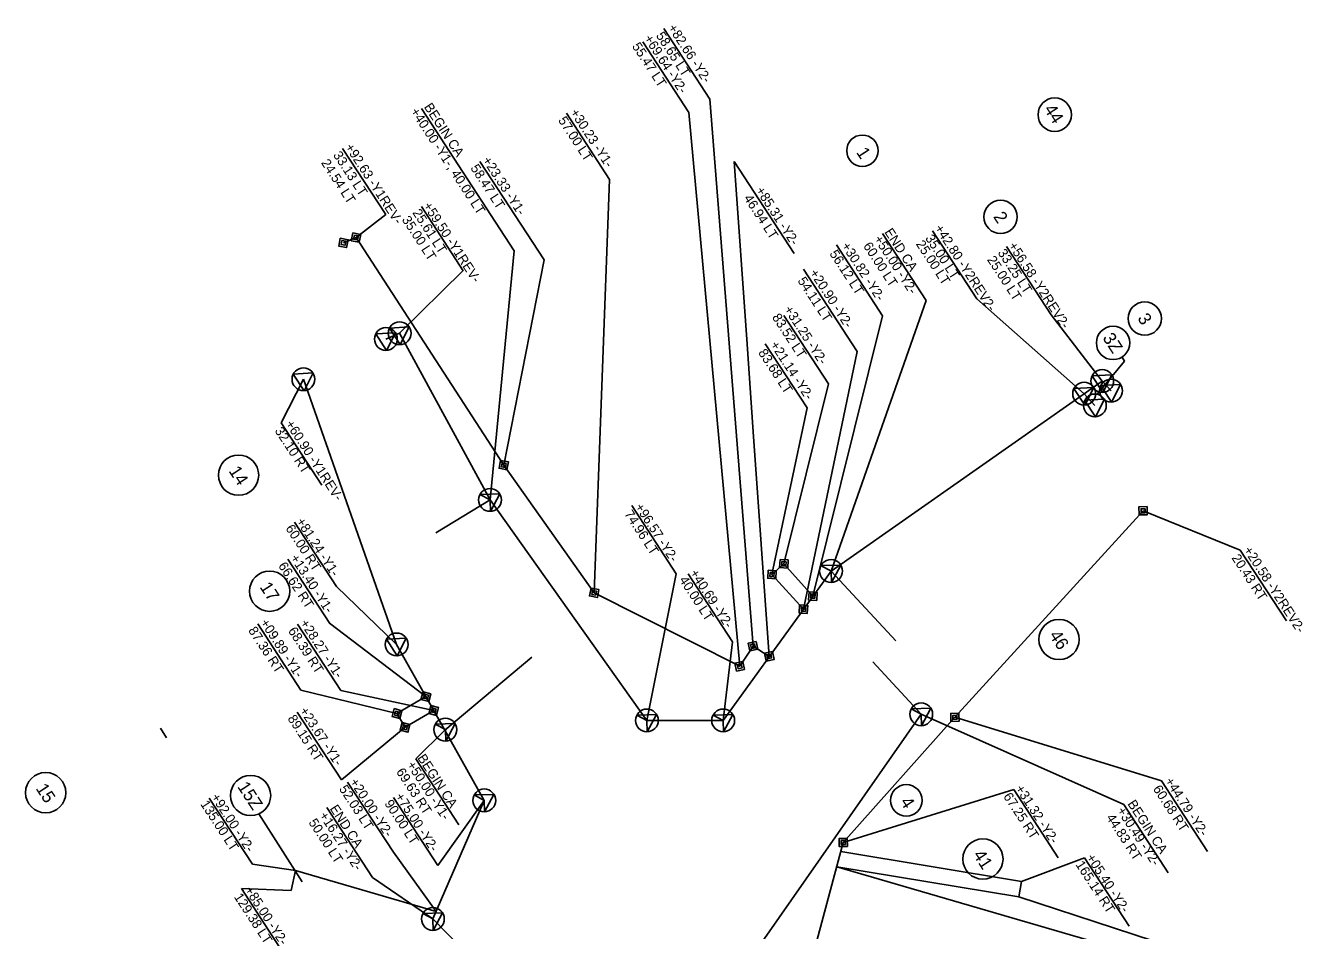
# Model space of a CAD drawing. Extents: x 1638966 to 1642158, y 841755 to 844938.
# Drawn here: x 1640014 to 1640818, y 843723 to 844293 of the extents above; entities that cross this region are included whole.
import ezdxf

# ---------------------------------------------------------------- set-up
doc = ezdxf.new("R2010")
doc.units = 0
for name, color, linetype in [('Exist Building', 7, 'Continuous'), ('Exist Guardrail Text', 7, 'Continuous'), ('Exist Other Culture Fence Line Text', 7, 'Continuous'), ('Exist Structure Major Deck Tunnel Box Culvert Text', 7, 'Continuous'), ('Exist Structure Minor Pipes CMP 18 Inch', 7, 'Continuous'), ('Exist Structure Minor Pipes CMP 18 Inch Text', 7, 'Continuous'), ('Exist Structure Minor Pipes CMP 24 Inch', 7, 'Continuous'), ('Exist Structure Minor Pipes RCP 24 Inch', 7, 'Continuous'), ('P_RDY_ROW_RW_CA_Lines', 7, 'Continuous'), ('Prop ROW Marker CELL', 7, 'Continuous')]:
    doc.layers.add(name, color=color, linetype=linetype)

msp = doc.modelspace()

# ---------------------------------------------------------------- linework, layer by layer
at = {"layer": 'Exist Building'}
for p, q in [((1640098.49, 843850.51), (1640102.45, 843844.41)), ((1640160.46, 843796.51), (1640187.9, 843753.69))]:
    msp.add_line(p, q, dxfattribs=at)
for centre, radius in [((1640662.07, 844237.1), 10.51), ((1640540.9, 844214.37), 9.91), ((1640627.96, 844172.72), 10.51), ((1640718.81, 844108.67), 10.51), ((1640698.83, 844093.26), 10.51), ((1640147.77, 844009.98), 12.69), ((1640167.33, 843936.85), 12.69), ((1640664.81, 843906.43), 12.69), ((1640026.21, 843809.9), 12.69), ((1640155.35, 843808.12), 12.69), ((1640568.57, 843805.06), 9.91), ((1640616.83, 843768.09), 12.69)]:
    msp.add_circle(centre, radius, dxfattribs=at)
at = {"layer": 'Exist Guardrail Text'}
for p, q in [((1640321.54, 844151.32), (1640263.07, 844240.92)), ((1640289.4, 844138.68), (1640262.98, 844179.16)), ((1640613.02, 844121.03), (1640585.03, 844163.91)), ((1640581.08, 844120.02), (1640553.55, 844162.22)), ((1640321.54, 844151.32), (1640306.22, 843994.38)), ((1640659.82, 844110.96), (1640631.72, 844154.04)), ((1640581.08, 844120.02), (1640521.15, 843949.58)), ((1640613.02, 844121.03), (1640680.64, 844061.31)), ((1640704.78, 844083.88), (1640706.1, 844081.85)), ((1640706.1, 844081.85), (1640689.1, 844061.24)), ((1640174.6, 844042.97), (1640188.67, 844070.41)), ((1640200.23, 844003.69), (1640174.6, 844042.97)), ((1640423.5, 843947.86), (1640395.51, 843990.75)), ((1640209.4, 843939.8), (1640182.99, 843980.29)), ((1640423.5, 843947.86), (1640405.08, 843855.41)), ((1640459.04, 843904.88), (1640431.05, 843947.77)), ((1640459.04, 843904.88), (1640453.14, 843855.41)), ((1640705.63, 843802.37), (1640577.95, 843859.33)), ((1640286.59, 843789.59), (1640259.38, 843831.27)), ((1640273.3, 843764.04), (1640245.31, 843806.93)), ((1640733.62, 843759.48), (1640705.63, 843802.37)), ((1640232.18, 843756.48), (1640203.41, 843800.57))]:
    msp.add_line(p, q, dxfattribs=at)
for points in [[(1640289.22, 844138.95), (1640249.26, 844099.4)], [(1640659.82, 844110.96), (1640692.03, 844069.29)], [(1640209.4, 843939.8), (1640247.36, 843903.31)], [(1640259.38, 843831.27), (1640277.72, 843849.27)], [(1640273.3, 843764.04), (1640302.59, 843805.03)], [(1640232.18, 843756.48), (1640270.22, 843730.36)]]:
    msp.add_lwpolyline(points, dxfattribs=at)
at = {"layer": 'Exist Other Culture Fence Line Text'}
msp.add_line((1640692.03, 844069.29), (1640697.57, 844063.19), dxfattribs=at)
for points in [[(1640240.62, 844095.75), (1640249.26, 844099.4), (1640306.22, 843994.38)], [(1640188.67, 844070.41), (1640247.36, 843903.31), (1640277.72, 843849.27)], [(1640521.15, 843949.58), (1640692.03, 844069.29), (1640697.57, 844063.19)], [(1640692.1, 844069.21), (1640697.57, 844063.19)], [(1640680.64, 844061.31), (1640680.64, 844061.31), (1640687.39, 844053.88)]]:
    msp.add_lwpolyline(points, dxfattribs=at)
at = {"layer": 'Exist Structure Major Deck Tunnel Box Culvert Text'}
for p in [(1640247.36, 843903.31), (1640332.48, 843895.24)]:
    msp.add_line(p, (1640277.72, 843849.27), dxfattribs=at)
for points in [[(1640272.02, 843973.64), (1640306.22, 843994.38)], [(1640521.15, 843949.58), (1640561.86, 843905.5)], [(1640547.53, 843892.27), (1640577.95, 843859.33)], [(1640270.22, 843730.36), (1640305.26, 843694.61)]]:
    msp.add_lwpolyline(points, dxfattribs=at)
at = {"layer": 'Exist Structure Minor Pipes CMP 18 Inch'}
for p, q in [((1640183.57, 843760.95), (1640180.92, 843748.31)), ((1640183.57, 843760.95), (1640272.26, 843735.04)), ((1640524.73, 843763.24), (1640639.54, 843744.24))]:
    msp.add_line(p, q, dxfattribs=at)
for points in [[(1640641.15, 843753.94), (1640641.15, 843753.94), (1640527.33, 843772.9)], [(1640639.54, 843744.24), (1640641.15, 843753.94)]]:
    msp.add_lwpolyline(points, dxfattribs=at)
at = {"layer": 'Exist Structure Minor Pipes CMP 18 Inch Text'}
for p, q in [((1640245.3, 843772.35), (1640216.48, 843816.53)), ((1640156.54, 843764.86), (1640129.34, 843806.54)), ((1640781.19, 843688.57), (1640524.73, 843763.24)), ((1640680.8, 843768.91), (1640641.15, 843753.94)), ((1640708.99, 843725.71), (1640680.8, 843768.91)), ((1640178.92, 843704.51), (1640149.58, 843749.48)), ((1640149.58, 843749.48), (1640180.92, 843748.31)), ((1640788.22, 843695.73), (1640639.54, 843744.24))]:
    msp.add_line(p, q, dxfattribs=at)
for points in [[(1640245.3, 843772.35), (1640272.26, 843735.04)], [(1640156.54, 843764.86), (1640183.57, 843760.95)]]:
    msp.add_lwpolyline(points, dxfattribs=at)
at = {"layer": 'Exist Structure Minor Pipes CMP 24 Inch'}
for p, q in [((1640444.78, 844246.89), (1640415.7, 844291.45)), ((1640431.52, 844238.43), (1640402.44, 844282.99)), ((1640444.78, 844246.89), (1640471.96, 843902.22)), ((1640381.62, 844196.34), (1640354.42, 844238.02)), ((1640431.52, 844238.43), (1640463.59, 843889.52)), ((1640240.57, 844174.1), (1640213.37, 844215.78)), ((1640340.27, 844145.63), (1640299.84, 844207.58)), ((1640497.89, 844149.54), (1640460.03, 844207.57)), ((1640460.03, 844207.57), (1640468.2, 844092.6)), ((1640381.62, 844196.34), (1640371.88, 843935.85)), ((1640553.61, 844110.44), (1640524.53, 844155.01)), ((1640340.27, 844145.63), (1640314.89, 844016.29)), ((1640537.54, 844087.83), (1640503.7, 844139.69)), ((1640519.56, 844067.44), (1640491.38, 844110.64)), ((1640553.61, 844110.44), (1640509.69, 843933.71)), ((1640468.2, 844092.6), (1640472.13, 844037.25)), ((1640506.09, 844052.33), (1640479.67, 844092.81)), ((1640537.54, 844087.83), (1640503.76, 843925.5)), ((1640519.56, 844067.44), (1640491.42, 843954.13)), ((1640506.09, 844052.33), (1640483.89, 843947.39)), ((1640472.13, 844037.25), (1640482.18, 843895.78)), ((1640808.11, 843918.23), (1640779.04, 843962.8)), ((1640205.23, 843916.47), (1640178.81, 843956.95)), ((1640187.09, 843874.55), (1640159.89, 843916.24)), ((1640212.19, 843874.29), (1640184.99, 843915.98)), ((1640205.12, 843916.63), (1640265.83, 843870.44)), ((1640212.59, 843817.95), (1640184.7, 843860.7)), ((1640729.28, 843817.47), (1640599.2, 843857.39)), ((1640758.35, 843772.91), (1640729.28, 843817.47)), ((1640636.24, 843811.93), (1640528.84, 843778.51)), ((1640664.35, 843768.85), (1640636.24, 843811.93))]:
    msp.add_line(p, q, dxfattribs=at)
for points in [[(1640240.57, 844174.1), (1640221.79, 844159.66)], [(1640779.04, 843962.8), (1640717.79, 843987.53)], [(1640187.09, 843874.55), (1640247.61, 843859.75)], [(1640212.19, 843874.29), (1640270.73, 843861.72)], [(1640212.59, 843817.95), (1640252.67, 843851.12)]]:
    msp.add_lwpolyline(points, dxfattribs=at)
at = {"layer": 'Exist Structure Minor Pipes RCP 24 Inch'}
for p, q in [((1640213.88, 844156.32), (1640213.88, 844156.32)), ((1640221.79, 844159.66), (1640221.79, 844159.66)), ((1640314.89, 844016.29), (1640314.89, 844016.29)), ((1640717.79, 843987.53), (1640599.2, 843857.39)), ((1640717.79, 843987.53), (1640717.79, 843987.53)), ((1640483.89, 843947.39), (1640491.42, 843954.13)), ((1640491.42, 843954.13), (1640509.69, 843933.71)), ((1640491.42, 843954.13), (1640491.42, 843954.13)), ((1640503.76, 843925.5), (1640483.89, 843947.39)), ((1640483.89, 843947.39), (1640483.89, 843947.39)), ((1640371.88, 843935.85), (1640371.88, 843935.85)), ((1640509.69, 843933.71), (1640509.69, 843933.71)), ((1640503.76, 843925.5), (1640503.76, 843925.5)), ((1640471.96, 843902.22), (1640471.96, 843902.22)), ((1640482.18, 843895.78), (1640482.18, 843895.78)), ((1640463.59, 843889.52), (1640463.59, 843889.52)), ((1640265.83, 843870.44), (1640247.61, 843859.75)), ((1640265.83, 843870.44), (1640265.83, 843870.44)), ((1640247.61, 843859.75), (1640252.67, 843851.12)), ((1640247.61, 843859.75), (1640247.61, 843859.75)), ((1640252.67, 843851.12), (1640270.73, 843861.72)), ((1640270.73, 843861.72), (1640270.73, 843861.72)), ((1640252.67, 843851.12), (1640252.67, 843851.12)), ((1640599.2, 843857.39), (1640528.84, 843778.51)), ((1640599.2, 843857.39), (1640599.2, 843857.39)), ((1640528.84, 843778.51), (1640499.38, 843668.98)), ((1640528.84, 843778.51), (1640528.84, 843778.51))]:
    msp.add_line(p, q, dxfattribs=at)
for points in [[(1640211.88, 844159.31), (1640216.87, 844158.33), (1640215.89, 844153.34), (1640210.89, 844154.32)], [(1640212.88, 844157.82), (1640215.38, 844157.33), (1640214.89, 844154.83), (1640212.39, 844155.32)], [(1640219.79, 844162.65), (1640224.78, 844161.67), (1640223.8, 844156.67), (1640218.8, 844157.66)], [(1640220.79, 844161.16), (1640223.29, 844160.67), (1640222.79, 844158.17), (1640220.3, 844158.66)], [(1640312.88, 844019.27), (1640317.88, 844018.29), (1640316.89, 844013.3), (1640311.9, 844014.28)], [(1640313.89, 844017.78), (1640316.38, 844017.29), (1640315.89, 844014.79), (1640313.39, 844015.28)], [(1640720.29, 843990.13), (1640720.38, 843985.04), (1640715.3, 843984.94), (1640715.19, 843990.03)], [(1640719.04, 843988.83), (1640719.09, 843986.29), (1640716.54, 843986.24), (1640716.49, 843988.78)], [(1640489.02, 843956.81), (1640494.11, 843956.53), (1640493.82, 843951.45), (1640488.74, 843951.73)], [(1640490.22, 843955.47), (1640492.76, 843955.33), (1640492.62, 843952.79), (1640490.08, 843952.93)], [(1640481.49, 843950.07), (1640486.57, 843949.79), (1640486.29, 843944.71), (1640481.2, 843944.99)], [(1640482.69, 843948.73), (1640485.23, 843948.59), (1640485.09, 843946.05), (1640482.54, 843946.19)], [(1640369.88, 843938.84), (1640374.87, 843937.86), (1640373.89, 843932.86), (1640368.89, 843933.85)], [(1640370.88, 843937.35), (1640373.38, 843936.85), (1640372.89, 843934.36), (1640370.39, 843934.85)], [(1640507.29, 843936.4), (1640512.38, 843936.11), (1640512.09, 843931.03), (1640507.01, 843931.31)], [(1640508.49, 843935.05), (1640511.03, 843934.91), (1640510.89, 843932.37), (1640508.35, 843932.51)], [(1640501.36, 843928.19), (1640506.45, 843927.9), (1640506.16, 843922.82), (1640501.08, 843923.1)], [(1640502.56, 843926.85), (1640505.11, 843926.7), (1640504.96, 843924.16), (1640502.42, 843924.3)], [(1640473.94, 843905.22), (1640474.96, 843900.24), (1640469.97, 843899.21), (1640468.95, 843904.2)], [(1640472.95, 843903.72), (1640473.46, 843901.23), (1640470.97, 843900.71), (1640470.45, 843903.21)], [(1640484.16, 843898.78), (1640485.19, 843893.8), (1640480.2, 843892.77), (1640479.17, 843897.76)], [(1640465.57, 843892.53), (1640466.59, 843887.54), (1640461.61, 843886.51), (1640460.58, 843891.5)], [(1640464.58, 843891.02), (1640465.09, 843888.53), (1640462.6, 843888.02), (1640462.09, 843890.51)], [(1640483.17, 843897.28), (1640483.68, 843894.79), (1640481.19, 843894.28), (1640480.68, 843896.77)], [(1640264.01, 843873.55), (1640268.93, 843872.26), (1640267.65, 843867.34), (1640262.72, 843868.62)], [(1640264.92, 843871.99), (1640267.38, 843871.35), (1640266.74, 843868.89), (1640264.28, 843869.53)], [(1640245.79, 843862.85), (1640250.71, 843861.57), (1640249.43, 843856.65), (1640244.5, 843857.93)], [(1640246.7, 843861.3), (1640249.16, 843860.66), (1640248.52, 843858.2), (1640246.06, 843858.84)], [(1640268.91, 843864.82), (1640273.84, 843863.54), (1640272.55, 843858.62), (1640267.63, 843859.9)], [(1640269.82, 843863.27), (1640272.28, 843862.63), (1640271.64, 843860.17), (1640269.18, 843860.81)], [(1640601.7, 843859.99), (1640601.8, 843854.9), (1640596.71, 843854.8), (1640596.61, 843859.89)], [(1640600.45, 843858.69), (1640600.5, 843856.14), (1640597.96, 843856.09), (1640597.9, 843858.64)], [(1640250.84, 843854.22), (1640255.77, 843852.94), (1640254.49, 843848.02), (1640249.56, 843849.3)], [(1640251.75, 843852.67), (1640254.22, 843852.03), (1640253.58, 843849.57), (1640251.11, 843850.21)], [(1640531.34, 843781.1), (1640531.44, 843776.01), (1640526.35, 843775.91), (1640526.25, 843781)], [(1640530.09, 843779.8), (1640530.14, 843777.26), (1640527.59, 843777.21), (1640527.54, 843779.75)]]:
    msp.add_lwpolyline(points, close=True, dxfattribs=at)
msp.add_lwpolyline([(1640213.88, 844156.32), (1640221.79, 844159.66), (1640314.89, 844016.29), (1640371.88, 843935.85), (1640463.59, 843889.52), (1640471.96, 843902.22), (1640482.18, 843895.78)], dxfattribs=at)
at = {"layer": 'P_RDY_ROW_RW_CA_Lines'}
for p, q in [((1640306.22, 843994.38), (1640405.08, 843855.41)), ((1640453.14, 843855.41), (1640521.15, 843949.58)), ((1640577.95, 843859.33), (1640459.09, 843689.48)), ((1640405.08, 843855.41), (1640453.14, 843855.41)), ((1640277.72, 843849.27), (1640302.59, 843805.03)), ((1640302.59, 843805.03), (1640270.22, 843730.36))]:
    msp.add_line(p, q, dxfattribs=at)
at = {"layer": 'Prop ROW Marker CELL'}
for p, q in [((1640249.26, 844099.4), (1640249.26, 844099.4)), ((1640240.62, 844095.75), (1640240.62, 844095.75)), ((1640188.67, 844070.41), (1640188.67, 844070.41)), ((1640692.03, 844069.29), (1640692.03, 844069.29)), ((1640680.64, 844061.31), (1640680.64, 844061.31)), ((1640697.57, 844063.19), (1640697.57, 844063.19)), ((1640687.39, 844053.88), (1640687.39, 844053.88)), ((1640299.88, 843997.81), (1640312.35, 843998.17)), ((1640306.22, 843994.38), (1640299.88, 843997.81)), ((1640306.44, 843987.17), (1640306.22, 843994.38)), ((1640312.35, 843998.17), (1640306.44, 843987.17)), ((1640514.8, 843953), (1640527.28, 843953.36)), ((1640521.15, 843949.58), (1640514.8, 843953)), ((1640521.37, 843942.37), (1640521.15, 843949.58)), ((1640527.28, 843953.36), (1640521.37, 843942.37)), ((1640247.36, 843903.31), (1640247.36, 843903.31)), ((1640398.73, 843858.84), (1640411.21, 843859.2)), ((1640405.08, 843855.41), (1640398.73, 843858.84)), ((1640411.21, 843859.2), (1640405.3, 843848.2)), ((1640446.8, 843858.84), (1640459.27, 843859.2)), ((1640453.14, 843855.41), (1640446.8, 843858.84)), ((1640459.27, 843859.2), (1640453.36, 843848.2)), ((1640571.6, 843862.76), (1640584.08, 843863.12)), ((1640577.95, 843859.33), (1640571.6, 843862.76)), ((1640578.17, 843852.12), (1640577.95, 843859.33)), ((1640584.08, 843863.12), (1640578.17, 843852.12)), ((1640271.75, 843853.06), (1640284.23, 843853.42)), ((1640278.1, 843849.64), (1640271.75, 843853.06)), ((1640278.32, 843842.43), (1640278.1, 843849.64)), ((1640284.23, 843853.42), (1640278.32, 843842.43)), ((1640405.3, 843848.2), (1640405.08, 843855.41)), ((1640453.36, 843848.2), (1640453.14, 843855.41)), ((1640296.24, 843808.45), (1640308.71, 843808.81)), ((1640302.59, 843805.03), (1640296.24, 843808.45)), ((1640302.81, 843797.82), (1640302.59, 843805.03)), ((1640308.71, 843808.81), (1640302.81, 843797.82)), ((1640263.88, 843733.79), (1640276.35, 843734.14)), ((1640270.22, 843730.36), (1640263.88, 843733.79)), ((1640270.44, 843723.15), (1640270.22, 843730.36)), ((1640276.35, 843734.14), (1640270.44, 843723.15))]:
    msp.add_line(p, q, dxfattribs=at)
for points in [[(1640234.19, 844099.02), (1640246.65, 844099.69), (1640241.02, 844088.55)], [(1640242.83, 844102.67), (1640255.29, 844103.34), (1640249.66, 844092.2)], [(1640182.24, 844073.67), (1640194.7, 844074.34), (1640189.07, 844063.2)], [(1640685.59, 844072.55), (1640698.06, 844073.22), (1640692.43, 844062.08)], [(1640691.14, 844066.45), (1640703.6, 844067.12), (1640697.97, 844055.99)], [(1640674.21, 844064.58), (1640686.67, 844065.25), (1640681.04, 844054.11)], [(1640680.96, 844057.15), (1640693.42, 844057.82), (1640687.79, 844046.68)], [(1640240.93, 843906.58), (1640253.39, 843907.25), (1640247.76, 843896.11)]]:
    msp.add_lwpolyline(points, close=True, dxfattribs=at)
for centre in [(1640240.62, 844095.75), (1640249.26, 844099.4), (1640188.67, 844070.41), (1640692.03, 844069.29), (1640680.64, 844061.31), (1640697.57, 844063.19), (1640687.39, 844053.88), (1640306.22, 843994.38), (1640521.15, 843949.58), (1640247.36, 843903.31), (1640577.95, 843859.33), (1640405.08, 843855.41), (1640453.14, 843855.41), (1640278.1, 843849.64), (1640302.59, 843805.03), (1640270.22, 843730.36)]:
    msp.add_circle(centre, 7.2, dxfattribs=at)

# ---------------------------------------------------------------- texts
at = {"layer": 'Exist Building'}
for s, p in [('44', (1640655.03, 844240.57)), ('1', (1640536.75, 844213.4)), ('2', (1640623.11, 844172.84)), ('3', (1640713.96, 844108.79)), ('3Z', (1640691.96, 844096.46)), ('14', (1640141.26, 844012.63)), ('17', (1640160.82, 843939.51)), ('46', (1640658.31, 843909.09)), ('15', (1640019.7, 843812.56)), ('15Z', (1640146.76, 843813.7)), ('4', (1640564.42, 843804.1)), ('41', (1640610.33, 843770.75))]:
    msp.add_text(s, height=8, rotation=303.09057, dxfattribs=at).set_placement(p)
at = {"layer": 'Exist Guardrail Text'}
for s, p in [('BEGIN CA', (1640264.37, 844242.02)), ('+40.00 -Y1-, 40.00 LT', (1640255.85, 844239.11)), ('+59.50 -Y1REV-', (1640263.82, 844179.7)), ('35.00 LT', (1640250.42, 844170.96)), ('25.61 LT', (1640257.12, 844175.33)), ('END CA', (1640554.56, 844163.14)), ('+42.80 -Y2REV2-', (1640586.13, 844165.51)), ('60.00 LT', (1640541.16, 844154.39)), ('+50.00 -Y2-', (1640547.86, 844158.76)), ('25.00 LT', (1640574.36, 844155.64)), ('35.00 LT', (1640580.24, 844159.24)), ('+56.58 -Y2REV2-', (1640632.62, 844154.49)), ('25.00 LT', (1640619.22, 844145.75)), ('33.25 LT', (1640625.92, 844150.12)), ('+60.90 -Y1REV-', (1640177.01, 844042.29)), ('32.10 RT', (1640170.31, 844037.92)), ('74.96 LT', (1640390.61, 843985.57)), ('+96.57 -Y2-', (1640397.3, 843989.95)), ('60.00 RT', (1640177.12, 843976.46)), ('+81.24 -Y1-', (1640183.82, 843980.83)), ('+40.69 -Y2-', (1640431.89, 843948.31)), ('40.00 LT', (1640425.19, 843943.94)), ('BEGIN CA', (1640260.22, 843831.82)), ('+50.00 -Y1-', (1640253.52, 843827.44)), ('69.63 RT', (1640246.82, 843823.07)), ('END CA', (1640205.03, 843799.91)), ('90.00 LT', (1640239.45, 843803.1)), ('+75.00 -Y2-', (1640246.15, 843807.47)), ('BEGIN CA', (1640707.69, 843802.92)), ('50.00 LT', (1640191.63, 843791.17)), ('+16.27 -Y2-', (1640198.33, 843795.54)), ('44.83 RT', (1640694.29, 843794.17)), ('+30.49 -Y2-', (1640700.99, 843798.55))]:
    msp.add_text(s, height=6, rotation=303.12591, dxfattribs=at).set_placement(p)
at = {"layer": 'Exist Structure Minor Pipes CMP 18 Inch Text'}
for s, p in [('+20.00 -Y2-', (1640217.57, 843816.69)), ('52.03 LT', (1640210.87, 843812.31)), ('135.00 LT', (1640123.48, 843802.72)), ('+92.00 -Y2-', (1640130.18, 843807.09)), ('+05.40 -Y2-', (1640681.7, 843768.98)), ('165.14 RT', (1640675, 843764.61)), ('129.38 LT', (1640144.64, 843744.23)), ('+85.00 -Y2-', (1640151.34, 843748.61))]:
    msp.add_text(s, height=6, rotation=303.12591, dxfattribs=at).set_placement(p)
at = {"layer": 'Exist Structure Minor Pipes CMP 24 Inch'}
for s, p in [('+82.66 -Y2-', (1640418.11, 844291.83)), ('+69.64 -Y2-', (1640403.02, 844285.11)), ('58.65 LT', (1640410.57, 844286.91)), ('55.47 LT', (1640395.48, 844280.2)), ('57.00 LT', (1640348.94, 844233.57)), ('+30.23 -Y1-', (1640356.48, 844238.49)), ('33.13 LT', (1640207.09, 844211.68)), ('+92.63 -Y1REV-', (1640214.63, 844216.6)), ('24.54 LT', (1640199.55, 844206.77)), ('58.47 LT', (1640293.65, 844203.46)), ('+23.33 -Y1-', (1640301.19, 844208.38)), ('+85.31 -Y2-', (1640473.43, 844189.39)), ('46.94 LT', (1640465.89, 844184.47)), ('+30.82 -Y2-', (1640527.44, 844154.41)), ('56.12 LT', (1640519.91, 844149.49)), ('54.11 LT', (1640499.81, 844132.48)), ('+20.90 -Y2-', (1640507.35, 844137.4)), ('+31.25 -Y2-', (1640491.24, 844114.37)), ('83.52 LT', (1640483.7, 844109.46)), ('+21.14 -Y2-', (1640482.54, 844092.05)), ('83.68 LT', (1640475, 844087.13)), ('+20.58 -Y2REV2-', (1640780.84, 843962.78)), ('66.62 RT', (1640172.53, 843952.85)), ('+13.40 -Y1-', (1640180.07, 843957.77)), ('20.43 RT', (1640773.3, 843957.86)), ('87.36 RT', (1640153.61, 843912.14)), ('+09.89 -Y1-', (1640161.15, 843917.06)), ('68.39 RT', (1640178.71, 843911.88)), ('+28.27 -Y1-', (1640186.25, 843916.79)), ('89.15 RT', (1640178.42, 843856.6)), ('+23.67 -Y1-', (1640185.95, 843861.52)), ('+44.79 -Y2-', (1640731.29, 843817.23)), ('67.25 RT', (1640629.46, 843807.56)), ('+31.32 -Y2-', (1640637, 843812.48)), ('60.68 RT', (1640723.76, 843812.31))]:
    msp.add_text(s, height=6, rotation=303.12591, dxfattribs=at).set_placement(p)

doc.saveas('drawing.dxf')
